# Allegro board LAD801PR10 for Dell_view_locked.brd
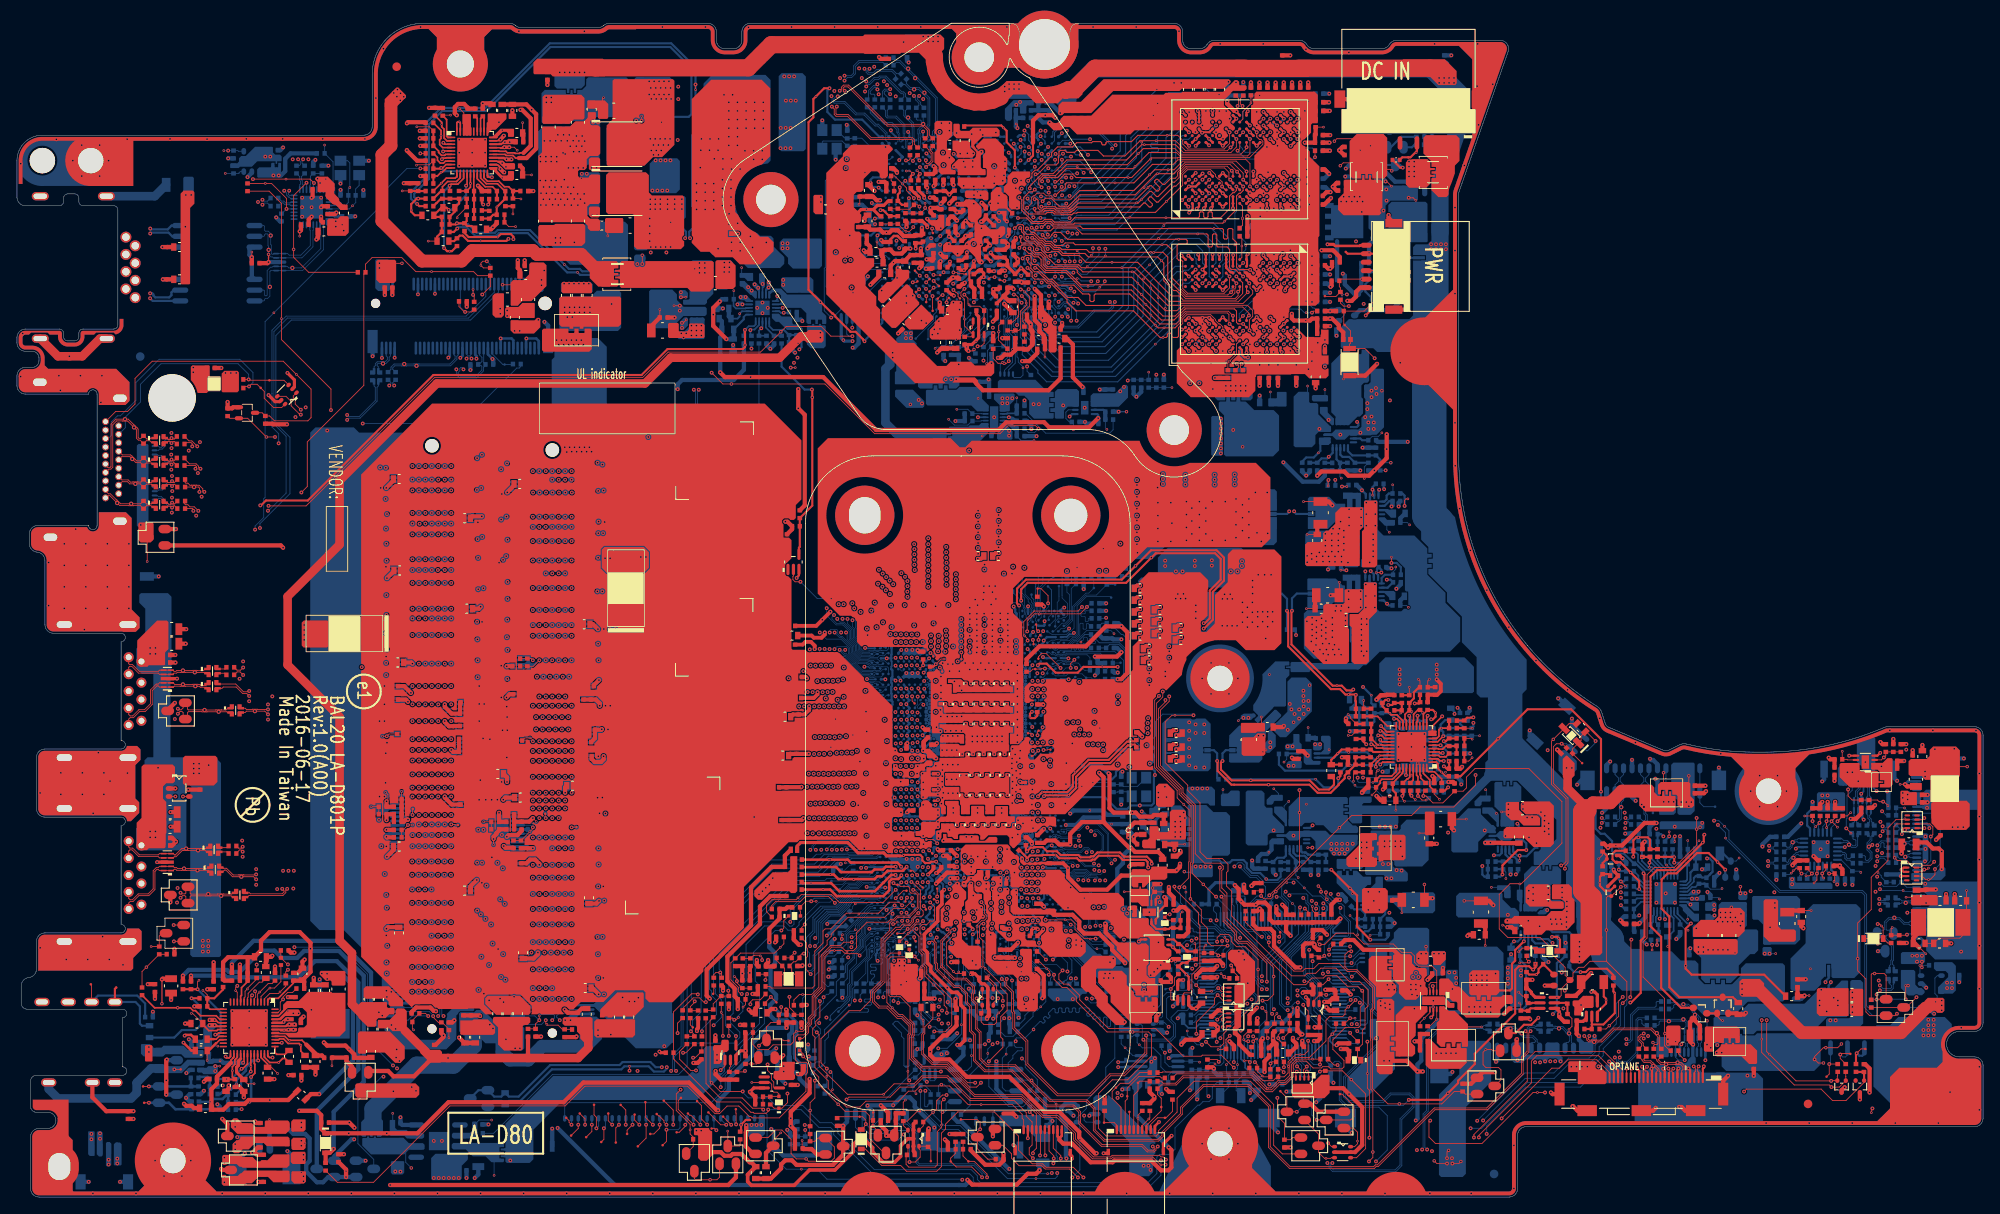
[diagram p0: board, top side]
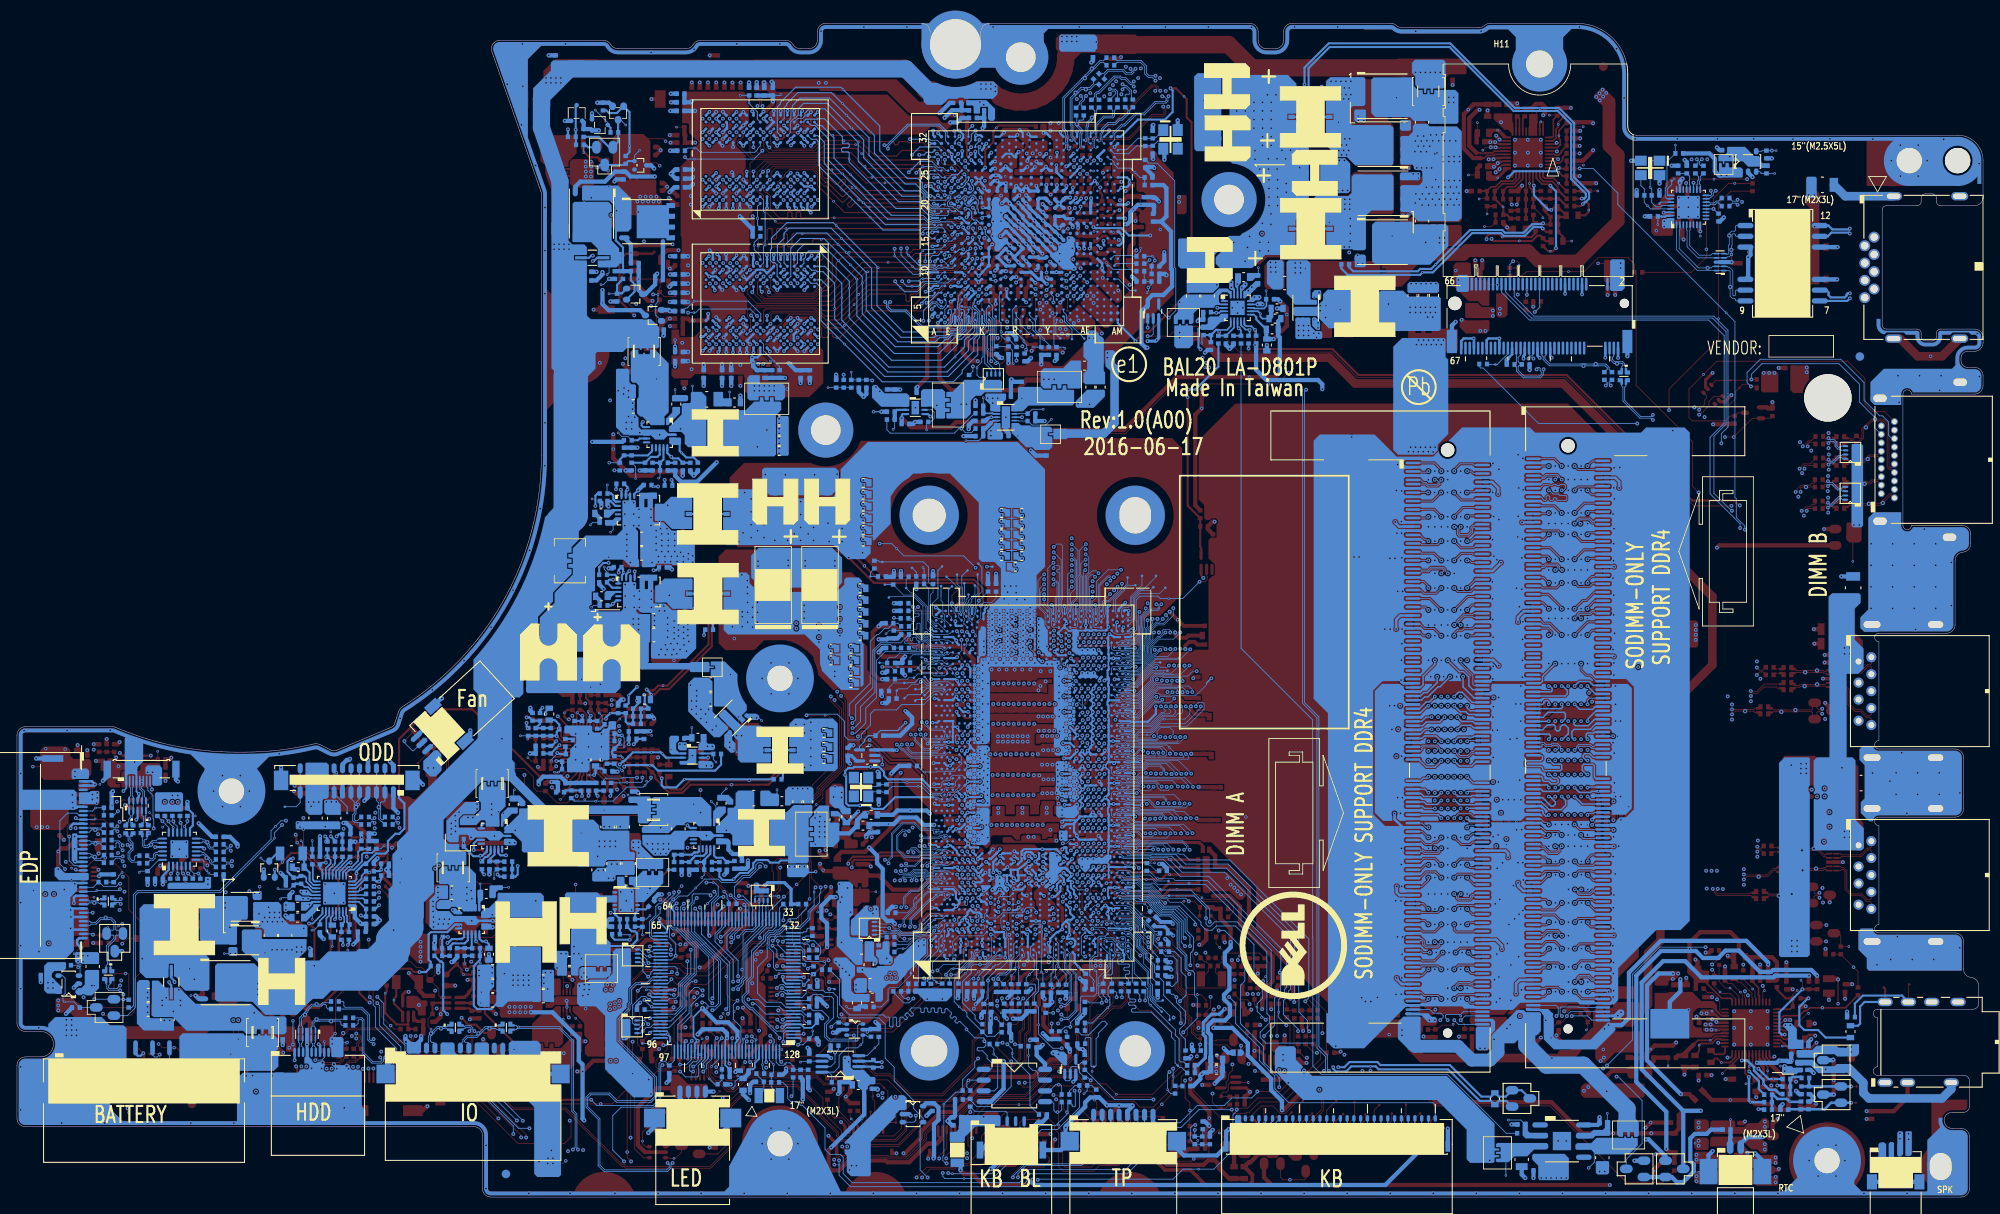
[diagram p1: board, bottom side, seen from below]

Outline 231.9 x 138.5 mm; copper layers: TOP, GND1, IN1, VCC, IN2, IN3, GND2, BOTTOM. Coordinates in mm from the lower left corner of the outline.
Outline path: 0,122.3 arc(0.88,124.42) 3,125.3 40.9,125.3 arc(41.61,125.59) 41.9,126.3 41.9,132.5 arc(43.66,136.74) 47.9,138.5 58.13,138.5 arc(58.49,138.44) 58.8,138.25 arc(59.1,138.06) 59.46,138 68.54,138 arc(68.9,138.06) 69.2,138.25 arc(69.51,138.44) 69.87,138.5 81.5,138.5 arc(82.21,138.21) 82.5,137.5 82.5,136.5 arc(82.79,135.79) 83.5,135.5 84.5,135.5 arc(85.21,135.79) 85.5,136.5 85.5,137.5 arc(85.79,138.21) 86.5,138.5 117.2,138.5 arc(117.91,138.21) 118.2,137.5 118.2,136 arc(121.2,133) 124.2,136 124.2,137.5 arc(124.49,138.21) 125.2,138.5 136.5,138.5 arc(137.21,138.21) 137.5,137.5 137.5,136.5 arc(137.79,135.79) 138.5,135.5 139.5,135.5 arc(140,135.63) 140.37,136 arc(140.73,136.37) 141.23,136.5 151.27,136.5 arc(151.77,136.37) 152.13,136 arc(152.5,135.63) 153,135.5 161,135.5 arc(161.5,135.63) 161.87,136 arc(162.23,136.37) 162.73,136.5 174.94,136.5 arc(175.76,136.08) 175.88,135.17 170.11,118.66 arc(170.06,118.5) 170.05,118.33 170.05,87.5 arc(174.41,70.58) 186.41,57.88 arc(186.71,57.6) 186.91,57.23 187.34,55.9 arc(187.51,55.61) 187.79,55.41 194.19,52.72 arc(194.52,52.66) 194.85,52.74 196.1,53.36 arc(196.5,53.48) 196.92,53.46 arc(200.96,52.74) 205.05,52.5 206.05,52.5 arc(213.3,53.24) 220.25,55.42 arc(220.44,55.48) 220.64,55.5 230.9,55.5 arc(231.61,55.21) 231.9,54.5 231.9,20.54 arc(231.61,19.83) 230.9,19.54 229.1,19.54 arc(227.6,18.04) 229.1,16.54 230.9,16.54 arc(231.61,16.25) 231.9,15.54 231.9,9.3 arc(231.61,8.59) 230.9,8.3 178,8.3 arc(177.29,8.01) 177,7.3 177,1 arc(176.71,0.29) 176,0 2.6,0 arc(1.89,0.29) 1.6,1 1.6,7.1 arc(1.89,7.81) 2.6,8.1 3.65,8.1 arc(4.6,9.05) 3.65,10 2.3,10 arc(1.8,10.21) 1.6,10.7 1.6,13.67 arc(1.8,14.16) 2.3,14.37 12.45,14.37 arc(12.95,14.87) 12.45,15.37 12.45,21.17 arc(12.95,21.67) 12.45,22.17 1.2,22.17 arc(0.71,22.37) 0.5,22.87 0.5,24.91 arc(0.76,25.58) 1.4,25.9 arc(2.04,26.23) 2.3,26.9 2.3,30.17 arc(2.59,30.87) 3.3,31.17 12.28,31.17 arc(12.78,31.67) 12.28,32.17 12.28,43.83 arc(12.78,44.33) 12.28,44.83 3.3,44.83 arc(2.59,45.13) 2.3,45.83 2.3,51.87 arc(2.59,52.57) 3.3,52.87 12.28,52.87 arc(12.78,53.37) 12.28,53.87 12.28,65.53 arc(12.78,66.03) 12.28,66.53 4.3,66.53 arc(3.59,66.83) 3.3,67.53 3.3,75.1 arc(3.03,75.78) 2.38,76.1 arc(1.73,76.42) 1.46,77.09 1.46,78.25 arc(1.75,78.96) 2.46,79.25 8.45,79.25 arc(8.95,78.75) 9.45,79.25 9.45,94.75 arc(8.95,95.25) 8.45,94.75 1,94.75 arc(0.29,95.04) 0,95.75 0,96.9 arc(0.29,97.61) 1,97.9 1.8,97.9 arc(2.37,98.13) 2.6,98.7 2.6,99 arc(2.37,99.57) 1.8,99.8 1,99.8 arc(0.29,100.09) 0,100.8 0,101.42 arc(0.29,102.13) 1,102.42 5,102.42 arc(5.35,102.28) 5.5,101.92 5.5,101.52 arc(5.65,101.17) 6,101.02 6.8,101.02 arc(7.15,101.17) 7.3,101.52 7.3,101.92 arc(7.45,102.28) 7.8,102.42 11.4,102.42 arc(11.75,102.57) 11.9,102.92 11.9,116.48 arc(11.75,116.83) 11.4,116.98 7.8,116.98 arc(7.45,117.12) 7.3,117.48 7.3,117.88 arc(7.15,118.23) 6.8,118.38 6,118.38 arc(5.65,118.23) 5.5,117.88 5.5,117.48 arc(5.35,117.12) 5,116.98 1,116.98 arc(0.29,117.27) 0,117.98 0,122.3

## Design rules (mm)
net group AUD_SPK_L_C: nets AUD_SPK_L+_C AUD_SPK_L-_C
net group AUD_SPK_R_C: nets AUD_SPK_R+_C AUD_SPK_R-_C
net group AUDIO: nets DMIC_CLK DMIC_CLK_EDP
net group CB: nets CBN CBP
net group DDR-RESET: nets DDR4_DRAMRST# H_DRAMRST#
net group DP: nets CPU_DP3_AUXN CPU_DP3_AUXP
net group GT1: nets GT1N GT1P
net group HDMI_15: nets HDMI_HPD_B HDMI_PLL_GND
net group ISUM_GT: nets ISUMN_GT ISUMP_GT
net group ISUM_IA: nets ISUMN_IA ISUMP_IA
net group ISUM_VSA: nets ISUMN_VSA ISUMP_VSA
net group NCT7718_DX: nets NCT7718_DXN NCT7718_DXP
net group PCH_SMBCLK: nets PCH_SMBCLK PCH_SMBDATA
net group PCIE_CTX_C_SSDRX_P11: nets PCIE_CTX_C_SSDRX_N11 PCIE_CTX_C_SSDRX_P11
net group PCIE_CTX_C_SSDRX_P12: nets PCIE_CTX_C_SSDRX_N12 PCIE_CTX_C_SSDRX_P12
net group PCIE_RCOMP: nets PCIE_RCOMPN PCIE_RCOMPP
net group SML1CLK: nets SML1CLK SML1DATA
net group USB_PP6_C: nets USB_PN6_C USB_PP6_C
net group VSA_SEN: nets VSA_SEN+ VSA_SEN-
net group VSUM_VGA: nets VSUM+_VGA VSUM-_VGA
net group ASYNCHRONOUS SIGNALS: nets H_THERMTRIP#
net group ASYNCHRONOUS-SIGNALS: nets PECI_MEC1404 VIDALERT_N VIDSOUT XDP_OBS2_R XDP_OBS3_R
net group CLK: nets H_PROCHOT#
net group CLK-SINGLE: nets CLK_ITPXDP_P
net group CLOCK-S: nets CLK_PCI_LPDEBUG
net group DDR_A-CLK: nets DDR_A_CLK0 DDR_A_CLK1 DDR_A_CLK#0 DDR_A_CLK#1
net group DDR_A-CMD: nets DDR_A_ACT# DDR_A_ALERT# DDR_A_BG0 DDR_A_BG1 DDR_A_BS0 DDR_A_BS1 DDR_A_CAS# DDR_A_MA0 DDR_A_MA1 DDR_A_MA2 DDR_A_MA3 DDR_A_MA4 DDR_A_MA5 DDR_A_MA6 DDR_A_MA7 DDR_A_MA8 DDR_A_MA9 DDR_A_MA10 DDR_A_MA11 DDR_A_MA12 DDR_A_MA13 DDR_A_PAR DDR_A_RAS# DDR_A_WE#
net group DDR_A-CTRL: nets DDR_A_CKE0 DDR_A_CKE1 DDR_A_CKE2 DDR_A_CKE3 DDR_A_CS#0 DDR_A_CS#1 DDR_A_ODT0 DDR_A_ODT1
net group DDR_A-D0: nets DDR_A_D0 DDR_A_D1 DDR_A_D2 DDR_A_D3 DDR_A_D4 DDR_A_D5 DDR_A_D6 DDR_A_D7
net group DDR_A-D1: nets DDR_A_D8 DDR_A_D9 DDR_A_D10 DDR_A_D11 DDR_A_D12 DDR_A_D13 DDR_A_D14 DDR_A_D15
net group DDR_A-D2: nets DDR_A_D16 DDR_A_D17 DDR_A_D18 DDR_A_D19 DDR_A_D20 DDR_A_D21 DDR_A_D22 DDR_A_D23
net group DDR_A-D3: nets DDR_A_D24 DDR_A_D25 DDR_A_D26 DDR_A_D27 DDR_A_D28 DDR_A_D29 DDR_A_D30 DDR_A_D31
net group DDR_A-D4: nets DDR_A_D32 DDR_A_D33 DDR_A_D34 DDR_A_D35 DDR_A_D36 DDR_A_D37 DDR_A_D38 DDR_A_D39
net group DDR_A-D5: nets DDR_A_D40 DDR_A_D41 DDR_A_D42 DDR_A_D43 DDR_A_D44 DDR_A_D45 DDR_A_D46 DDR_A_D47
net group DDR_A-D6: nets DDR_A_D48 DDR_A_D49 DDR_A_D50 DDR_A_D51 DDR_A_D52 DDR_A_D53 DDR_A_D54 DDR_A_D55
net group DDR_A-D7: nets DDR_A_D56 DDR_A_D57 DDR_A_D58 DDR_A_D59 DDR_A_D60 DDR_A_D61 DDR_A_D62 DDR_A_D63
net group DDR_B-CLK: nets DDR_B_CLK0 DDR_B_CLK1 DDR_B_CLK#0 DDR_B_CLK#1
net group DDR_B-CMD: nets DDR_B_ACT# DDR_B_ALERT# DDR_B_BG0 DDR_B_BG1 DDR_B_BS0 DDR_B_BS1 DDR_B_CAS# DDR_B_MA0 DDR_B_MA1 DDR_B_MA2 DDR_B_MA3 DDR_B_MA4 DDR_B_MA5 DDR_B_MA6 DDR_B_MA7 DDR_B_MA8 DDR_B_MA9 DDR_B_MA10 DDR_B_MA11 DDR_B_MA12 DDR_B_MA13 DDR_B_PAR DDR_B_RAS# DDR_B_WE#
net group DDR_B-CTRL: nets DDR_B_CKE0 DDR_B_CKE1 DDR_B_CKE2 DDR_B_CKE3 DDR_B_CS#0 DDR_B_CS#1 DDR_B_ODT0 DDR_B_ODT1
net group DDR_B-D0: nets DDR_B_D0 DDR_B_D1 DDR_B_D2 DDR_B_D3 DDR_B_D4 DDR_B_D5 DDR_B_D6 DDR_B_D7
net group DDR_B-D1: nets DDR_B_D8 DDR_B_D9 DDR_B_D10 DDR_B_D11 DDR_B_D12 DDR_B_D13 DDR_B_D14 DDR_B_D15
net group DDR_B-D2: nets DDR_B_D16 DDR_B_D17 DDR_B_D18 DDR_B_D19 DDR_B_D20 DDR_B_D21 DDR_B_D22 DDR_B_D23
net group DDR_B-D3: nets DDR_B_D24 DDR_B_D25 DDR_B_D26 DDR_B_D27 DDR_B_D28 DDR_B_D29 DDR_B_D30 DDR_B_D31
net group DDR_B-D4: nets DDR_B_D32 DDR_B_D33 DDR_B_D34 DDR_B_D35 DDR_B_D36 DDR_B_D37 DDR_B_D38 DDR_B_D39
net group DDR_B-D5: nets DDR_B_D40 DDR_B_D41 DDR_B_D42 DDR_B_D43 DDR_B_D44 DDR_B_D45 DDR_B_D46 DDR_B_D47
net group DDR_B-D6: nets DDR_B_D48 DDR_B_D49 DDR_B_D50 DDR_B_D51 DDR_B_D52 DDR_B_D53 DDR_B_D54 DDR_B_D55
net group DDR_B-D7: nets DDR_B_D56 DDR_B_D57 DDR_B_D58 DDR_B_D59 DDR_B_D60 DDR_B_D61 DDR_B_D62 DDR_B_D63
net group DDR_DQS: nets DDR_A_DQS0 DDR_A_DQS1 DDR_A_DQS2 DDR_A_DQS3 DDR_A_DQS4 DDR_A_DQS5 DDR_A_DQS6 DDR_A_DQS7 DDR_A_DQS#0 DDR_A_DQS#1 DDR_A_DQS#2 DDR_A_DQS#3 DDR_A_DQS#4 DDR_A_DQS#5 DDR_A_DQS#6 DDR_A_DQS#7 DDR_B_DQS0 DDR_B_DQS1 DDR_B_DQS2 DDR_B_DQS3 DDR_B_DQS4 DDR_B_DQS5 DDR_B_DQS6 DDR_B_DQS7 DDR_B_DQS#0 DDR_B_DQS#1 DDR_B_DQS#2 DDR_B_DQS#3 DDR_B_DQS#4 DDR_B_DQS#5 DDR_B_DQS#6 DDR_B_DQS#7
net group DMIC: nets DMIC_DATA_EDP
net group EDP: nets EDP_AUX EDP_AUX# EDP_AUX_DN EDP_AUX_DP EDP_TX0 EDP_TX0# EDP_TX0_DN EDP_TX0_DP EDP_TX1 EDP_TX1# EDP_TX1_DN EDP_TX1_DP
net group EDP-RCOMP: nets EDP_COMP
net group EMC: nets BST1_VGA BST2_VGA BST_1.2V BST_1.2V_R BST_3V BST_5V BST_+1VALW BST_+1VALW_R GT_SW1 LANXIN LANXOUT LG1_VGA LG2_VGA LG_1.2V LGATE_CHG LX1_VGA LX2_VGA LX_1.2V LX_1.8VALW LX_3V LX_5V LX_+1VALW MCT0 MCT1 MEC_XTAL1 MEC_XTAL1_R MEC_XTAL2 PHASE_CHG SA_SW UG1_VGA UG2_VGA UG_1.2V UGATE_CHG
net group ESD: nets DRAM_RST H_CPUPWRGD H_CPUPWRGD_R IMVP_VR_ON PCH_DPWROK PCH_PLTRST# PCH_PLTRST#_EC PCH_RSMRST# POWER_SW#_MB POWER_SW_IN# RESET_OUT# RUNPWROK SIO_PWRBTN# SIO_SLP_S3# SYS_PWROK SYS_RESET# USB_OC#0_1 USB_OC#2_3 USB_OC#4_5
net group GPU-XTAL: nets XTALOUT
net group GSPI: nets 3D_CAM_EN 3D_CAM_EN_PCH FW_UPDATE FW_UPDATE_PCH NRB_BIT
net group HDA: nets HDA_CODEC_RST# HDA_CODEC_SDIN0 HDA_CODEC_SDOUT HDA_CODEC_SYNC HDA_RST# HDA_SDIN0 HDA_SDOUT HDA_SYNC
net group HDMI: nets HDMI_CLK HDMI_CLK# HDMI_CLK#_R HDMI_CLK#_R_C HDMI_CLK_R HDMI_CLK_R_C HDMI_DATA0 HDMI_DATA0# HDMI_DATA0#_R HDMI_DATA0#_R_C HDMI_DATA0_R HDMI_DATA0_R_C HDMI_DATA1 HDMI_DATA1# HDMI_DATA1#_R HDMI_DATA1#_R_C HDMI_DATA1_R HDMI_DATA1_R_C HDMI_DATA2 HDMI_DATA2# HDMI_DATA2#_R HDMI_DATA2#_R_C HDMI_DATA2_R HDMI_DATA2_R_C
net group I2C: nets DDC_CLK_HDMI DDC_DATA_HDMI I2C_SCL_TP I2C_SDA_TP I2C_SDA_TP_Q PCH_HDMI_CLK PCH_HDMI_DATA
net group KB: nets KB_DET# KSI0 KSI1 KSI2 KSI3 KSI4 KSI5 KSI6 KSI7 KSO0 KSO1 KSO2 KSO3 KSO4 KSO5 KSO6 KSO7 KSO8 KSO9 KSO10 KSO11 KSO12 KSO13 KSO14 KSO15 KSO16
net group LAN: nets LAN_MDI0N LAN_MDI0P LAN_MDI1N LAN_MDI1P
net group LPC: nets LPC_LAD0 LPC_LAD1 LPC_LAD2 LPC_LAD3
net group MDI: nets MDO0+ MDO0- MDO1+ MDO1-
net group PCIE: nets LAN_TXN_C_PCH_RXN6 LAN_TXP_C_PCH_RXP6 PCIE_CRX_LANTX_N6 PCIE_CRX_LANTX_P6 PCIE_CRX_SSDTX_N11 PCIE_CRX_SSDTX_N12 PCIE_CRX_SSDTX_P11 PCIE_CRX_SSDTX_P12 PCIE_CRX_WLANTX_N5 PCIE_CRX_WLANTX_P5 PCIE_CTX_LANRX_N6 PCIE_CTX_LANRX_P6 PCIE_CTX_SSDRX_N11 PCIE_CTX_SSDRX_N12 PCIE_CTX_SSDRX_P11 PCIE_CTX_SSDRX_P12 PCIE_CTX_WLANRX_N5 PCIE_CTX_WLANRX_N5_C PCIE_CTX_WLANRX_P5 PCIE_CTX_WLANRX_P5_C PCIE_PTX_LANRX_N6_C PCIE_PTX_LANRX_P6_C PEG_GTX_C_HRX_N0 PEG_GTX_C_HRX_N1 PEG_GTX_C_HRX_N2 PEG_GTX_C_HRX_N3 PEG_GTX_C_HRX_P0 PEG_GTX_C_HRX_P1 PEG_GTX_C_HRX_P2 PEG_GTX_C_HRX_P3 PEG_GTX_HRX_N0 PEG_GTX_HRX_N1 PEG_GTX_HRX_N2 PEG_GTX_HRX_N3 PEG_GTX_HRX_P0 PEG_GTX_HRX_P1 PEG_GTX_HRX_P2 PEG_GTX_HRX_P3 PEG_HTX_C_GRX_N0 PEG_HTX_C_GRX_N1 PEG_HTX_C_GRX_N2 PEG_HTX_C_GRX_N3 PEG_HTX_C_GRX_P0 PEG_HTX_C_GRX_P1 PEG_HTX_C_GRX_P2 PEG_HTX_C_GRX_P3 PEG_HTX_GRX_N0 PEG_HTX_GRX_N1 PEG_HTX_GRX_N2 PEG_HTX_GRX_N3 PEG_HTX_GRX_P0 PEG_HTX_GRX_P1 PEG_HTX_GRX_P2 PEG_HTX_GRX_P3
net group PLATFORM-CLK: nets CLK_ITPXDP_N CLK_PCIE_LAN_N2 CLK_PCIE_LAN_P2 CLK_PCIE_LAN_REQ# CLK_PCIE_LAN_REQ#_R CLK_PCIE_SSD_N3 CLK_PCIE_SSD_P3 CLK_PCIE_SSD_REQ# CLK_PCIE_WLAN_N1 CLK_PCIE_WLAN_P1 CLK_PCIE_WLAN_REQ# CLK_PCIE_WLAN_REQ#_R CLK_PEG_VGA# PCI_CLK_LPC1 PEG_CLKREQ# PEG_CLKREQ#_G XCLK_BIASREF XTAL24_IN XTAL24_OUT
net group RTC: nets PCH_RTCX2 PCH_RTCX2_R SRTCRST#
net group SATA: nets SATA3_CRX_HDDTX_N0 SATA3_CRX_HDDTX_P0 SATA3_CTX_HDDRX_N0 SATA3_CTX_HDDRX_P0 SATA_CRX_ODDTX_N1 SATA_CRX_ODDTX_P1 SATA_CTX_ODDRX_N1 SATA_CTX_ODDRX_P1 SATA_RXN0_R SATA_RXN2_R SATA_RXP0_R SATA_RXP2_R SATA_TXN0_R SATA_TXN2_R SATA_TXP0_R SATA_TXP2_R
net group SMBUS: nets CLK_SMB DAT_SMB PBAT_CHG_SMBDAT PCH_SMB_ALERT# SMBCLK SMBDATA SML0_SMBCLK SML0_SMBDATA THM_SML1_CLK THM_SML1_DATA VGA_SMB_CK3 VGA_SMB_DA3
net group SPACING-8: nets AUD_HP1_JACK_L AUD_HP1_JACK_L1 AUD_HP1_JACK_R AUD_HP1_JACK_R1 HPOUT_L HPOUT_R LINE1-L_C LINE1-L_R LINE1_L LINE1_R
net group SPACING-12: nets H_PROCHOT#_R SATA_LED# SATA_ODD_PRSNT# VCCST_PWRGD
net group SPACING-15: nets +MVREFSA CFG0 CFG1 CFG2 CFG3 CFG4 CFG5 CFG6 CFG7 CFG8 CFG9 CFG10 CFG11 CFG12 CFG13 CFG14 CFG15 CFG16 CFG17 CFG18 CFG19 CFG_RCOMP CLK_PCI_LPC_MEC CPU_XDP_TCK0 EC_SPI_CLK H_CATERR# H_VCCST_PWRGD HDA_BIT_CLK HDA_CODEC_BITCLK I2C_SCL_TP_Q PBAT_CHG_SMBCLK PCH_JTAG_TCK1 PCH_RTCRST# PCH_RTCX1 PCH_SPI_CLK_0_R PCH_SPI_CLK_R RING2 RING2_R SLEEVE SLEEVE_R SOC_XDP_TDI SOC_XDP_TDO SOC_XDP_TMS SOC_XDP_TRST# SUSCLK SUSCLK_EC SUSCLK_SSD SVI2_SVC SVI2_SVD SVI2_SVT USBCOMP XDP_OBS0_R XDP_OBS1_R XDP_PRDY# XDP_PREQ#
net group SPACING-18(15): nets N26505655 N26505677 PECI_EC VIDSCLK
net group SPACING-20: nets SM_RCOMP0 SM_RCOMP1 SM_RCOMP2
net group SPI: nets EC_SPI_CS0# EC_SPI_MISO EC_SPI_MOSI N28938912 PCH_SPI_CLK_R1 PCH_SPI_CS#0_R1 PCH_SPI_D0_0_R PCH_SPI_D0_R PCH_SPI_D0_R1 PCH_SPI_D1_0_R PCH_SPI_D1_R PCH_SPI_D1_R1 PCH_SPI_D2_0_R PCH_SPI_D2_R PCH_SPI_D2_R1 PCH_SPI_D3_0_R PCH_SPI_D3_R PCH_SPI_D3_R1
net group SPK: nets AUD_SPK_L+ AUD_SPK_L- AUD_SPK_R+ AUD_SPK_R-
net group SVID: nets H_CPU_SVIDALRT#
net group USB20: nets USB_CAMERA_EDP USB_CAMERA_EDP# USB_PN1 USB_PN1_C USB_PN2 USB_PN2_C USB_PN3 USB_PN3_C USB_PN5 USB_PN6 USB_PN7 USB_PN7_TPNL USB_PN8 USB_PN8_R USB_PP1 USB_PP1_C USB_PP2 USB_PP2_C USB_PP3 USB_PP3_C USB_PP5 USB_PP6 USB_PP7 USB_PP7_TPNL USB_PP8 USB_PP8_R
net group USB30: nets USB3_CRX_C_RD_DTX_N3 USB3_CRX_C_RD_DTX_P3 USB3_CRX_DTX_N1 USB3_CRX_DTX_N1_C USB3_CRX_DTX_N2 USB3_CRX_DTX_N2_C USB3_CRX_DTX_N3 USB3_CRX_DTX_P1 USB3_CRX_DTX_P1_C USB3_CRX_DTX_P2 USB3_CRX_DTX_P2_C USB3_CRX_DTX_P3 USB3_CRX_L_DTX_N3 USB3_CRX_L_DTX_P3 USB3_CRX_RD_DTX_N3 USB3_CRX_RD_DTX_P3 USB3_CTX_C_DRX_N3 USB3_CTX_C_DRX_P3 USB3_CTX_C_RD_DRX_N3 USB3_CTX_C_RD_DRX_P3 USB3_CTX_DRX_N1 USB3_CTX_DRX_N1_C USB3_CTX_DRX_N1_R USB3_CTX_DRX_N2 USB3_CTX_DRX_N2_C USB3_CTX_DRX_N2_R USB3_CTX_DRX_N3 USB3_CTX_DRX_P1 USB3_CTX_DRX_P1_C USB3_CTX_DRX_P1_R USB3_CTX_DRX_P2 USB3_CTX_DRX_P2_C USB3_CTX_DRX_P2_R USB3_CTX_DRX_P3 USB3_CTX_L_DRX_N3 USB3_CTX_L_DRX_P3 USB3_CTX_RD_DRX_N3 USB3_CTX_RD_DRX_P3
net group VRAM-CLK: nets M_CLK0 M_CLK1 M_CLK#0 M_CLK#1
net group VRAM-DBI: nets M_ADBI0 M_ADBI1 M_DBI0# M_DBI1# M_DBI2# M_DBI3# M_DBI4# M_DBI5# M_DBI6# M_DBI7#
net group VRAM-EDC: nets M_EDC_0 M_EDC_1 M_EDC_2 M_EDC_3 M_EDC_4 M_EDC_5 M_EDC_6 M_EDC_7
net group VRAM-WCK: nets M_WCKA0_0 M_WCKA0_0# M_WCKA0_1 M_WCKA0_1# M_WCKA1_0 M_WCKA1_0# M_WCKA1_1 M_WCKA1_1#
net group VRAM_CMD: nets M_CAS#0 M_CAS#1 M_CKE0 M_CKE1 M_CS0B#0 M_CS1B#0 M_RAS#0 M_RAS#1 M_WE#0 M_WE#1
net group VRAM_D0: nets M_DA0 M_DA1 M_DA2 M_DA3 M_DA4 M_DA5 M_DA6 M_DA7
net group VRAM_D1: nets M_DA8 M_DA9 M_DA10 M_DA11 M_DA12 M_DA13 M_DA14 M_DA15
net group VRAM_D2: nets M_DA16 M_DA17 M_DA18 M_DA19 M_DA20 M_DA21 M_DA22 M_DA23
net group VRAM_D3: nets M_DA24 M_DA25 M_DA26 M_DA27 M_DA28 M_DA29 M_DA30 M_DA31
net group VRAM_D4: nets M_DA32 M_DA33 M_DA34 M_DA35 M_DA36 M_DA37 M_DA38 M_DA39
net group VRAM_D5: nets M_DA40 M_DA41 M_DA42 M_DA43 M_DA44 M_DA45 M_DA46 M_DA47
net group VRAM_D6: nets M_DA48 M_DA49 M_DA50 M_DA51 M_DA52 M_DA53 M_DA54 M_DA55
net group VRAM_D7: nets M_DA56 M_DA57 M_DA58 M_DA59 M_DA60 M_DA61 M_DA62 M_DA63
net group VRAM_MA: nets M0_MA0 M0_MA1 M0_MA2 M0_MA3 M0_MA4 M0_MA5 M0_MA6 M0_MA7 M0_MA8 M1_MA0 M1_MA1 M1_MA2 M1_MA3 M1_MA4 M1_MA5 M1_MA6 M1_MA7 M1_MA8
net group XDP: nets PCH_RSMRST#_Q XDP_HOOK0 XDP_ITP_PMODE XDP_PRSENT_CPU XDP_SPI_IO2 XDP_SPI_SI
net group XTAL-15(18)-20(26): nets XTALIN
nets with their own width: min track width 0.254; nets CAP_LED EN_1.8VALW FB_1.8VALW JACK_PLUG V3D3_STB
nets with their own width: min track width 0.508; nets +0.6V_DDR_VTT +0.6VSP +0.95VSDGPU +0.95VSDGPU_ON +0.95VSDGPU_OUT +1.0V_AMPHYPLL +1.0V_APLL +1.0V_APLLEBB +1.0V_CLK2 +1.0V_CLK4 +1.0V_CLK5 +1.0V_MPHYGT +1.0V_PRIM +1.0V_SRAM +1.0V_VCCST +1.0V_VCCST_C +1.0V_VCCSTG +1.0V_XDP +1.0VS_VCCIO +1.2V_DDR +1.2VP +1.8V_AVDD +1.8V_PRIM +1.8VALWP +1.8VGS +1.8VGS_GPU_ON +1.8VGS_OUT +1VALWP +2.5V_MEM +2.5VP +3.3V_ALW_DSW +3.3V_SPI +3.3V_WLAN +3V_DVDD +3VALW +3VALW_EC +3VALW_PCH +3VALWP +3VGS +3VGS_GPU_ON +3VGS_OUT +3VLP +3VS +3VS_CAM +5V_AVDD +5V_CAM +5V_KB_BL +5V_PVDD +5VALW +5VALWP +5VS +17.4V_BATT+ +17.4V_BATT++ +19V_ADPIN +19V_VIN +19VB +19VB_1.2V +19VB_+1VALW +19VB_GPU +BIF_VDDC +DCBAT_CAM +DCBAT_LCD +DP_VDDC +DP_VDDR +FB0_VREFCL +FB0_VREFDL +FB1_VREFCL +FB1_VREFDL +LAN_VDD10 +LAN_VDD33 +LAN_VDDREG +LCDVDD +LCDVDD_LCD +MIC2-VREFO +MPLL_PVDD +MVREFDA +RTC_CELL +RTC_CELL_VBAT +RTC_VCC +SPLL_PVDD +SPLL_VDDC +TP_VDD +TPAN_VDD +TSVDD +V_DDR_REFA +V_DDR_REFA_R +V_DDR_REFB +V_DDR_REFB_R +VCC_CORE +VCC_CORE_G0 +VCC_CORE_G1 +VCC_GT +VCC_SA +VDD_CT +VDDR3 +VGA_CORE ACIN_CHG AUD_AGND EC_AGND GND RTC_PWR
nets with their own width: min track width 1.016; nets MCT
nets with their own width: min track width 2.032; nets USB20_VCCA

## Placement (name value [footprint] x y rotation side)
C1  0.47U_0402_6.3V6K  [C_0402]  35.88 8.79 0 top
C2  0.1U_0402_16V7K  [C_0402]  223.78 47.46 0 top
C3  1U_0402_10V6K  [C_0402]  223.78 46.57 0 top
C4  0.1U_0603_50V7K  [C_0603]  224.75 51.27 90 top
C5  1000P_0402_50V7K  [C_0402]  223.6 51.19 90 top
C6  0.1U_0402_16V7K  [C_0402]  220.73 42.12 0 bottom
C7  0.1U_0402_16V7K  [C_0402]  220.73 41.24 0 bottom
C8  0.1U_0402_16V7K  [C_0402]  220.73 40.35 0 bottom
C9  0.1U_0402_16V7K  [C_0402]  220.73 39.46 0 bottom
C10  0.1U_0402_16V7K  [C_0402]  220.73 43.01 0 bottom
C11  0.1U_0402_16V7K  [C_0402]  220.73 43.9 0 bottom
C13  10P_0402_50V8J  [C_0402]  220.49 37.15 90 bottom
C14  33P_0402_50V8J  [C_0402]  225.19 35.38 90 top
C15  4.7U_0603_6.3V6K  [C_0603]  224.05 34.82 90 top
C16  10P_0402_50V8J  [C_0402]  222.01 30.9 270 top
C17  1U_0402_6.3V6K  [C_0402]  228.17 26.19 0 bottom
C18  .1U_0402_16V7K  [C_0402]  93.55 5.66 90 top
C19  0.1U_0402_16V7K  [C_0402]  103.66 9.89 180 top
C20  10U_0603_6.3V6M  [C_0603]  131.97 13.23 0 bottom
C21  0.1U_0402_16V7K  [C_0402]  131.06 13.69 270 bottom
C22  470P_0603_50V8J  [C_0603]  57.58 12.3 270 bottom
C23  2200P_0402_50V7K  [C_0402]  130.88 15.27 90 bottom
C24  0.1U_0402_16V7K  [C_0402]  135.79 13.55 180 bottom
C25  0.1U_0402_16V7K  [C_0402]  135.01 17.86 0 bottom
C26  10P_0402_50V8J  [C_0402]  110.72 5.65 180 top
C27  10P_0402_50V8J  [C_0402]  111.58 5.65 0 top
C30  22U_0805_10V6M  [C_0805]  194.48 45.55 270 bottom
C32  0.1U_0402_16V7K  [C_0402]  92.1 7.14 270 bottom
C33  100P_0402_50V8J  [C_0402]  92.98 7.15 270 bottom
C34  .1U_0402_16V7K  [C_0402]  120.53 8.47 0 bottom
CA1  10U_0603_10V6M  [C_0603]  35.01 23.65 90 top
CA2  .1U_0402_16V7K  [C_0402]  32.85 22.68 90 top
CA3  10U_0603_10V6M  [C_0603]  36.34 23.65 90 top
CA4  .1U_0402_16V7K  [C_0402]  33.48 19.63 90 top
CA5  4.7U_0603_6.3V6K  [C_0603]  28.02 28.34 0 top
CA6  .1U_0402_16V7K  [C_0402]  27.21 26.44 180 top
CA7  .1U_0402_16V7K  [C_0402]  22.45 22.5 180 top
CA9  6.8P_0402_50V  [C_0402]  31.12 29.1 0 top
CA10  .1U_0402_16V7K  [C_0402]  23.59 13.93 180 top
CA11  4.7U_0603_10V6K  [C_0603]  22.94 10.5 180 top
CA12  4.7U_0603_6.3V6K  [C_0603]  35.21 16.7 270 top
CA13  4.7U_0603_6.3V6K  [C_0603]  41.75 16.48 90 top
CA14  .1U_0402_16V7K  [C_0402]  40.65 16.42 90 top
CA15  4.7U_0603_6.3V6K  [C_0603]  33.67 25.61 90 top
CA16  .1U_0402_16V7K  [C_0402]  32.59 25.54 90 top
CA17  .1U_0402_16V7K  [C_0402]  27.21 25.55 180 top
CA20  4.7U_0603_6.3V6K  [C_0603]  24.66 12.47 90 top
CA21  10U_0603_6.3V6M  [C_0603]  33.98 15.31 90 top
CA22  4.7U_0603_6.3V6K  [C_0603]  29.36 27.2 270 top
CA23  2.2U_0603_6.3V6K  [C_0603]  26.75 13.87 270 top
CA24  1U_0603_16V7  [C_0603]  32.09 15.9 90 top
CA25  1U_0603_16V7  [C_0603]  29.56 13.92 90 top
CA26  10U_0603_6.3V6M  [C_0603]  21.93 20.47 180 top
CA27  1000P_0402_50V7K  [C_0402]  28.72 6.77 270 top
CA28  1000P_0402_50V7K  [C_0402]  28.72 7.82 90 top
CA29  1000P_0402_50V7K  [C_0402]  29.1 2.7 270 top
CA30  1000P_0402_50V7K  [C_0402]  29.1 4.08 90 top
CA31  0.1U_0402_16V7K  [C_0402]  14.75 24.73 270 top
CA32  10U_0603_10V6M  [C_0603]  22.43 17.3 180 top
CA33  10U_0603_10V6M  [C_0603]  22.43 18.63 180 top
CA34  100P_0402_50V8J  [C_0402]  20.53 13.05 270 bottom
CA35  100P_0402_50V8J  [C_0402]  20.59 10.36 90 bottom
CA36  100P_0402_50V8J  [C_0402]  20.7 15.92 270 bottom
CA37  100P_0402_50V8J  [C_0402]  20.59 16.9 90 bottom
CC1  0.1U_0402_16V7K  [C_0402]  90.82 77.29 90 top
CC2  33P_0402_50V8J  [C_0402]  104.6 11.76 90 bottom
CC3  0.1U_0402_25V6  [C_0402]  111.63 17.65 90 bottom
CC4  1U_0402_6.3V6K  [C_0402]  92.54 21.5 270 top
CC5  1U_0402_6.3V6K  [C_0402]  89.86 21.49 0 top
CC6  15P_0402_50V8J  [C_0402]  130.24 48.69 90 bottom
CC7  15P_0402_50V8J  [C_0402]  130.24 47.83 270 bottom
CC8  6.8P_0402_50V8C  [C_0402]  91.13 27.27 0 top
CC9  6.8P_0402_50V8C  [C_0402]  90.26 27.27 180 top
CC10  1U_0402_6.3V6K  [C_0402]  84.03 14.77 270 top
CC11  0.1U_0402_10V7K  [C_0402]  82.38 17.54 90 top
CC12  0.1U_0402_16V7K  [C_0402]  91.29 14.15 270 top
CC13  0.1U_0402_16V7K  [C_0402]  133.9 52.09 90 bottom
CC14  1U_0402_6.3V6K  [C_0402]  87.99 11.84 180 top
CC15  100P_0402_50V8J  [C_0402]  124.91 72.35 0 bottom
CC16  22P_0402_50V8J  [C_0402]  80.73 17.18 270 top
CC26  10U_0402_6.3V6M  [C_0402]  90.76 47.45 90 top
CC27  10U_0402_6.3V6M  [C_0402]  91.97 51.38 90 top
CC28  10U_0402_6.3V6M  [C_0402]  91.64 61.36 0 top
CC29  10U_0402_6.3V6M  [C_0402]  91.08 43.57 90 top
CC30  10U_0402_6.3V6M  [C_0402]  90.19 43.57 90 top
CC31  10U_0402_6.3V6M  [C_0402]  88.97 48.35 0 top
CC32  1U_0402_6.3V6K  [C_0402]  104.9 48.91 90 top
CC33  1U_0402_6.3V6K  [C_0402]  104.92 52.02 90 top
CC34  1U_0402_6.3V6K  [C_0402]  92.22 56.03 90 top
CC35  1U_0402_6.3V6K  [C_0402]  91.78 64.27 90 top
CC36  22U_0603_6.3V6M  [C_0603]  89.62 52.09 0 top
CC37  22U_0603_6.3V6M  [C_0603]  89.87 56.68 0 top
CC38  22U_0603_6.3V6M  [C_0603]  90.7 66.25 0 top
CC39  10U_0402_6.3V6M  [C_0402]  90.87 67.4 0 top
CC40  1U_0402_6.3V6K  [C_0402]  105.35 42.89 0 top
CC41  1U_0402_6.3V6K  [C_0402]  131.83 38.37 90 top
CC42  1U_0402_6.3V6K  [C_0402]  120.35 41.79 90 top
CC43  1U_0402_6.3V6K  [C_0402]  91.57 58.89 0 top
CC44  1U_0402_6.3V6K  [C_0402]  132.73 38.37 90 top
CC45  1U_0402_6.3V6K  [C_0402]  106.65 45.62 180 top
CC46  1U_0402_6.3V6K  [C_0402]  107.65 52.11 270 top
CC47  1U_0402_6.3V6K  [C_0402]  107.08 44.74 270 top
CC48  1U_0402_6.3V6K  [C_0402]  107.97 44.74 270 top
CC49  10U_0402_6.3V6M  [C_0402]  106.94 53.36 0 top
CC50  10U_0402_6.3V6M  [C_0402]  107.46 54.24 90 top
CC51  1U_0402_6.3V6K  [C_0402]  106.11 25.17 0 top
CC52  1U_0402_6.3V6K  [C_0402]  106.11 24.29 0 top
CC53  1U_0402_6.3V6K  [C_0402]  106.11 23.42 0 top
CC54  1U_0402_6.3V6K  [C_0402]  105.73 26.69 0 top
CC55  1U_0402_6.3V6K  [C_0402]  117.61 36.99 180 top
CC56  1U_0402_6.3V6K  [C_0402]  105.85 26.35 270 bottom
CC57  1U_0402_6.3V6K  [C_0402]  110 39.06 90 top
CC58  1U_0402_6.3V6K  [C_0402]  115.08 41.22 90 top
CC59  47U_0805_6.3V6M  [C_0805]  130.41 25 0 bottom
CC60  1U_0402_6.3V6K  [C_0402]  116.22 32.74 270 top
CC61  8.2P_0402_50V8D  [C_0402]  90.57 38.96 270 top
CC62  1U_0402_6.3V6K  [C_0402]  110.15 40.92 180 top
CC63  1U_0402_6.3V6K  [C_0402]  130.35 44.01 270 bottom
CC64  1U_0402_6.3V6K  [C_0402]  113.58 38.3 0 top
CC65  1P_0402_50V8  [C_0402]  109.02 38.92 180 top
CC66  1U_0402_6.3V6K  [C_0402]  114.45 35.44 180 top
CC67  1U_0402_6.3V6K  [C_0402]  133.2 31.55 0 bottom
CC68  1U_0402_6.3V6K  [C_0402]  111.25 34.56 0 top
CC69  0.1U_0402_10V7K  [C_0402]  97.01 29.84 180 bottom
CC70  0.1U_0402_10V7K  [C_0402]  90.75 35.52 90 top
CC71  1U_0402_6.3V6K  [C_0402]  89.85 35.52 90 top
CC72  1U_0402_6.3V6K  [C_0402]  116.86 28.26 90 top
CC73  0.1U_0402_10V7K  [C_0402]  132.56 26.9 90 bottom
CC74  47U_0805_6.3V6M  [C_0805]  131.44 29.45 0 bottom
CC75  1U_0402_6.3V6K  [C_0402]  120.26 33.69 90 top
CC76  47U_0603_6.3V6M  [C_0603]  136.53 41.63 270 top
CC77  47U_0603_6.3V6M  [C_0603]  135.25 45.08 90 top
CC78  0.1U_0402_10V7K  [C_0402]  113.47 36.32 180 top
CC79  1U_0402_6.3V6K  [C_0402]  133.22 32.42 0 bottom
CC80  22U_0603_6.3V6M  [C_0603]  91.09 16.25 180 bottom
CC81  22U_0603_6.3V6M  [C_0603]  91.12 15.03 180 bottom
CC82  8.2P_0402_50V8D  [C_0402]  133.04 41.64 180 top
CC83  0.1U_0603_25V7K  [C_0603]  132.8 44.18 270 top
CC84  47U_0603_6.3V6M  [C_0603]  134.08 44.16 90 bottom
CC85  1U_0402_6.3V6K  [C_0402]  110.83 21.18 90 top
CC86  1U_0402_6.3V6K  [C_0402]  111.82 27.75 180 top
CC87  1U_0402_6.3V6K  [C_0402]  115.97 28.27 90 top
CC88  10P_0402_50V8J  [C_0402]  94.06 17.29 270 bottom
CC89  1P_0402_50V8  [C_0402]  80.35 22.01 270 top
CC90  100P_0402_50V8J  [C_0402]  92.34 79.15 180 top
CD1  10U_0603_6.3V6M~D  [C_0603]  72.22 20.53 90 top
CD2  10U_0603_6.3V6M~D  [C_0603]  71.01 20.53 90 top
CD3  1U_0402_6.3V6K~D  [C_0402]  69.93 20.52 90 top
CD4  1U_0402_6.3V6K~D  [C_0402]  69.04 20.52 90 top
CD5  1U_0402_6.3V6K~D  [C_0402]  60.15 20.9 90 top
CD6  10U_0603_6.3V6M~D  [C_0603]  56.66 20.92 90 top
CD7  10U_0603_6.3V6M~D  [C_0603]  57.87 20.92 90 top
CD8  10U_0603_6.3V6M~D  [C_0603]  59.07 20.92 90 top
CD9  0.1U_0402_16V7K~D  [C_0402]  66.12 20.84 90 top
CD10  2.2U_0603_6.3V6K~D  [C_0603]  67.2 20.85 90 top
CD11  1U_0402_6.3V6K~D  [C_0402]  59.45 40.3 270 top
CD12  1U_0402_6.3V6K~D  [C_0402]  66.87 52.03 0 top
CD13  1U_0402_6.3V6K~D  [C_0402]  67.13 60.29 0 top
CD14  1U_0402_6.3V6K~D  [C_0402]  66.81 53.68 0 top
CD15  1U_0402_6.3V6K~D  [C_0402]  67.71 57.8 90 top
CD16  1U_0402_6.3V6K~D  [C_0402]  66.82 57.8 90 top
CD17  1U_0402_6.3V6K~D  [C_0402]  67.25 55.14 0 top
CD18  1U_0402_6.3V6K~D  [C_0402]  59.47 59.33 180 top
CD19  10U_0603_6.3V6M~D  [C_0603]  60.09 47.14 180 top
CD20  10U_0603_6.3V6M~D  [C_0603]  66.25 48.54 180 top
CD21  10U_0603_6.3V6M~D  [C_0603]  59.71 29.55 270 top
CD22  10U_0603_6.3V6M~D  [C_0603]  66.19 67.59 0 top
CD23  10U_0603_6.3V6M~D  [C_0603]  60.03 84.16 180 top
CD24  10U_0603_6.3V6M~D  [C_0603]  66.31 24.66 0 top
CD25  10U_0603_6.3V6M~D  [C_0603]  67.46 36.03 270 top
CD26  10U_0603_6.3V6M~D  [C_0603]  55.99 49.94 0 top
CD27  330U_D2_2V_Y  [C_D2]  41.83 66.5 180 top
CD28  0.1U_0402_16V7K~D  [C_0402]  59.52 44.3 270 top
CD29  0.1U_0402_16V7K~D  [C_0402]  59.35 62.65 180 top
CD30  0.022U_0402_25V7K  [C_0402]  56.86 43.39 180 top
CD31  1U_0402_6.3V6K~D  [C_0402]  44.21 21.98 90 top
CD32  10U_0603_6.3V6M~D  [C_0603]  41.93 20.53 270 top
CD33  10U_0603_6.3V6M~D  [C_0603]  41.48 22.63 90 top
CD34  10U_0603_6.3V6M~D  [C_0603]  42.69 22.63 90 top
CD35  1U_0402_6.3V6K~D  [C_0402]  52.66 20.52 90 top
CD36  1U_0402_6.3V6K~D  [C_0402]  53.55 20.52 90 top
CD37  10U_0603_6.3V6M~D  [C_0603]  54.06 19.58 270 top
CD38  10U_0603_6.3V6M~D  [C_0603]  52.85 19.58 270 top
CD39  0.1U_0402_16V7K~D  [C_0402]  45.1 21.98 90 top
CD40  2.2U_0603_6.3V6K~D  [C_0603]  43.14 20.53 270 top
CD41  1U_0402_6.3V6K~D  [C_0402]  44.01 58.7 0 top
CD42  1U_0402_6.3V6K~D  [C_0402]  44.01 60.29 0 top
CD43  1U_0402_6.3V6K~D  [C_0402]  53.24 46.32 180 top
CD44  1U_0402_6.3V6K~D  [C_0402]  53.05 52.54 180 top
CD45  1U_0402_6.3V6K~D  [C_0402]  53.05 54.06 180 top
CD46  1U_0402_6.3V6K~D  [C_0402]  53.18 55.59 180 top
CD47  1U_0402_6.3V6K~D  [C_0402]  53.18 57.05 180 top
CD48  1U_0402_6.3V6K~D  [C_0402]  53.24 58.38 180 top
CD49  10U_0603_6.3V6M~D  [C_0603]  52.09 36.16 0 top
CD50  10U_0603_6.3V6M~D  [C_0603]  52.09 80.1 0 top
CD51  10U_0603_6.3V6M~D  [C_0603]  44.21 63.08 0 top
CD52  10U_0603_6.3V6M~D  [C_0603]  45.87 73.94 180 top
CD53  10U_0603_6.3V6M~D  [C_0603]  45.8 84.73 180 top
CD54  10U_0603_6.3V6M~D  [C_0603]  45.8 41.36 180 top
CD55  10U_0603_6.3V6M~D  [C_0603]  52.34 69.43 0 top
CD56  10U_0603_6.3V6M~D  [C_0603]  45.04 30.44 90 top
CD57  330U_D2_2V_Y  [C_D2]  71.84 68.64 90 top
CD58  0.1U_0402_16V7K~D  [C_0402]  45.37 44.28 180 top
CD59  0.022U_0402_25V7K  [C_0402]  43.59 46.06 180 top
CE1  0.1U_0402_10V7K  [C_0402]  150.12 19.63 0 top
CE2  0.1U_0402_10V7K  [C_0402]  148.75 15.07 180 bottom
CE3  10P_0402_50V8J  [C_0402]  143.81 13.6 0 bottom
CE4  10P_0402_50V8J  [C_0402]  142.91 14.44 180 bottom
CE5  10U_0603_6.3V6M  [C_0603]  155.52 23.42 270 top
CE6  0.1U_0402_10V7K  [C_0402]  140.87 26.82 270 top
CE7  1000P_0402_50V7K  [C_0402]  146.84 32.8 0 top
CE8  1000P_0402_50V7K  [C_0402]  149.69 33.31 270 top
CE9  0.1U_0402_25V6  [C_0402]  152.86 32.42 270 top
CE10  0.1U_0402_25V6  [C_0402]  155.42 24.38 0 top
CE11  0.1U_0402_25V6  [C_0402]  151.8 17.73 180 top
CE12  0.1U_0402_25V6  [C_0402]  140.86 20.39 90 top
CE13  0.1U_0402_25V6  [C_0402]  146.77 16.7 0 top
CE14  0.1U_0402_10V7K  [C_0402]  145.61 14.91 0 bottom
CE15  0.1U_0402_25V6  [C_0402]  148.8 32.4 90 top
CE16  100P_0402_50V8J  [C_0402]  154.96 15.52 270 bottom
CE17  0.1U_0402_25V6  [C_0402]  157.12 18.13 270 top
CE18  0.1U_0402_10V7K  [C_0402]  154.12 33.36 0 top
CE19  0.047U_0402_16V4Z  [C_0402]  146.77 36.14 90 top
CE20  0.1U_0402_25V6  [C_0402]  140 26.83 270 top
CE21  0.1U_0402_25V6  [C_0402]  146.74 17.59 0 top
CE22  0.1U_0402_10V7K  [C_0402]  153.69 20.03 270 top
CE23  0.1U_0402_25V6  [C_0402]  140.01 28.79 270 top
CE24  1U_0603_16V7  [C_0603]  139.72 24.28 270 top
CE25  2200P_0402_25V7K  [C_0402]  149.45 18.06 180 top
CE26  47P_0402_50V8J  [C_0402]  152.29 20.03 270 top
CE27  0.047U_0402_16V4Z  [C_0402]  151.48 33.3 180 top
CE28  220P_0402_50V8J  [C_0402]  144.91 33.74 0 top
CE29  0.1U_0402_10V7K  [C_0402]  153.76 30.57 180 top
CE30  2200P_0402_25V7K  [C_0402]  148.32 20.46 270 top
CE31  1000P_0402_50V7K  [C_0402]  152.69 28.47 180 top
CE32  100P_0402_50V8J  [C_0402]  140.42 15.31 90 top
CE33  1U_0402_6.3V6K  [C_0402]  138.58 15.02 270 bottom
CI1  0.1U_0402_10V7K  [C_0402]  19.77 87.21 180 top
CI2  0.1U_0402_10V7K  [C_0402]  19.77 86.32 180 top
CI3  0.1U_0402_10V7K  [C_0402]  19.77 89.75 180 top
CI4  0.1U_0402_10V7K  [C_0402]  19.77 88.86 180 top
CI5  0.1U_0402_10V7K  [C_0402]  19.83 84.67 180 top
CI6  0.1U_0402_10V7K  [C_0402]  19.83 83.78 180 top
CI7  0.1U_0402_10V7K  [C_0402]  19.83 82.13 180 top
CI8  0.1U_0402_10V7K  [C_0402]  19.83 81.24 180 top
CI9  .1U_0402_16V7K  [C_0402]  22.4 97.83 0 top
CL1  0.1U_0402_10V7K  [C_0402]  32.98 121.7 270 bottom
CL2  0.1U_0402_10V7K  [C_0402]  33.93 121.7 270 bottom
CL3  0.1U_0402_10V7K  [C_0402]  29.91 116.93 0 bottom
CL4  0.1U_0402_10V7K  [C_0402]  29.91 117.88 0 bottom
CL5  0.1U_0402_25V6  [C_0402]  33.5 114.75 0 top
CL6  0.1U_0402_25V6  [C_0402]  36.65 115.99 90 top
CL7  4.7U_0603_6.3V6K  [C_0603]  36.91 113.94 180 top
CL8  0.1U_0402_25V6  [C_0402]  36.99 115.02 180 top
CL9  1U_0402_6.3V6K  [C_0402]  29.85 123.53 0 bottom
CL10  10P_0402_50V8J  [C_0402]  39.08 118.2 180 bottom
CL11  10P_0402_50V8J  [C_0402]  39.95 118.2 0 bottom
CL12  0.01U_0402_16V7K  [C_0402]  27.69 110.2 0 top
CL13  100P_1206_2KV8J  [C_1206]  20.26 119.44 180 bottom
CL14  0.1U_0402_25V6  [C_0402]  35.78 118.92 180 top
CS1  0.01U_0402_50V7K  [C_0402]  193.94 23.08 0 bottom
CS2  0.01U_0402_50V7K  [C_0402]  193.94 22.19 0 bottom
CS3  0.01U_0402_50V7K  [C_0402]  192.24 21.15 0 bottom
CS4  0.01U_0402_50V7K  [C_0402]  192.24 20.26 0 bottom
CS5  1000P_0402_50V7K  [C_0402]  199.42 18.76 180 top
CS6  0.1U_0402_25V6K  [C_0402]  199.42 19.65 180 top
CS7  10U_0805_10V6K  [C_0805]  195.64 19.07 0 top
CS9  0.01U_0402_50V7K  [C_0402]  191.29 43.97 180 bottom
CS10  0.01U_0402_50V7K  [C_0402]  191.29 44.85 180 bottom
CS11  0.01U_0402_50V7K  [C_0402]  188.5 43.97 180 bottom
CS12  0.01U_0402_50V7K  [C_0402]  188.5 44.85 180 bottom
CS13  1000P_0402_50V7K  [C_0402]  196.98 47.65 0 top
CS14  0.1U_0402_25V6K  [C_0402]  196.98 48.54 0 top
CS15  10U_0805_10V6K  [C_0805]  196.68 45.57 270 bottom
CS16  0.22U_0402_16V7K  [C_0402]  191.29 17.49 270 top
CS17  0.22U_0402_16V7K  [C_0402]  192.18 17.5 270 top
CS18  0.22U_0402_16V7K  [C_0402]  193.06 17.49 270 top
CS19  0.22U_0402_16V7K  [C_0402]  193.95 17.49 270 top
CU1  .1U_0402_16V7K  [C_0402]  25.62 62.51 180 top
CU2  .1U_0402_16V7K  [C_0402]  25.62 61.62 180 top
CU3  .1U_0402_16V7K  [C_0402]  25.88 41.43 180 top
CU4  .1U_0402_16V7K  [C_0402]  25.88 40.54 180 top
CU5  1U_0402_10V6K  [C_0402]  21.61 48.99 270 top
CU6  1U_0402_10V6K  [C_0402]  17.15 63.97 0 top
CU7  1U_0402_10V6K  [C_0402]  17.15 42.38 0 top
CU8  22U_0805_10V6M  [C_0805]  17.2 43.71 0 top
CU9  22U_0805_10V6M  [C_0805]  17.39 65.3 0 top
CU10  100U_1206_6.3V6M  [C_1206]  15.7 48.85 180 bottom
CU17  .1U_0402_16V7K  [C_0402]  123.93 11.07 270 bottom
CU18  1U_0402_10V6K  [C_0402]  17.15 63.07 0 top
CU19  1U_0402_10V6K  [C_0402]  17.15 41.48 0 top
CU20  22U_0805_10V6M  [C_0805]  17.39 67.01 0 top
CU21  22U_0805_10V6M  [C_0805]  17.2 45.42 0 top
CU22  100U_1206_6.3V6M  [C_1206]  15.32 70.57 90 bottom
CV1  0.22U_0402_16V7K  [C_0402]  100.28 129.51 270 bottom
CV2  0.22U_0402_16V7K  [C_0402]  101.18 129.51 270 bottom
CV3  0.22U_0402_16V7K  [C_0402]  102.09 129.49 270 bottom
CV4  0.22U_0402_16V7K  [C_0402]  102.99 129.49 270 bottom
CV5  0.22U_0402_16V7K  [C_0402]  106.23 123.85 270 top
CV6  0.22U_0402_16V7K  [C_0402]  105.33 123.85 270 top
CV7  0.22U_0402_16V7K  [C_0402]  107.12 124.93 270 top
CV8  0.22U_0402_16V7K  [C_0402]  108.01 124.93 270 top
CV11  0.082U_0402_16V  [C_0402]  103.9 114.83 90 top
CV15  0.68U_0402_10V  [C_0402]  103.45 118.69 180 top
CV17  10P_0402_50V8J  [C_0402]  97.94 124.92 90 bottom
CV18  10P_0402_50V8J  [C_0402]  97.94 124.05 270 bottom
CV19  10U_0603_6.3V6M  [C_0603]  100.31 114.47 90 top
CV20  1U_0402_6.3V4Z  [C_0402]  106.87 113.67 270 top
CV21  0.1U_0402_10V6K  [C_0402]  105.97 113.49 270 top
CV26  1U_0402_6.3V4Z  [C_0402]  103 111.78 90 top
CV27  10U_0603_6.3V6M  [C_0603]  102.02 111.51 180 top
CV28  0.68U_0402_10V  [C_0402]  105.79 117.08 180 top
CV29  0.68U_0402_10V  [C_0402]  106.6 116.09 270 top
CV30  10U_0603_6.3V6M  [C_0603]  104.71 110.43 270 top
CV33  1U_0402_6.3V4Z  [C_0402]  106.69 111.15 270 top
CV34  0.1U_0402_10V6K  [C_0402]  105.79 111.15 270 top
CV35  0.1U_0402_10V6K  [C_0402]  104.71 111.87 90 top
CV38  10U_0603_6.3V6M  [C_0603]  96.1 116.54 180 top
CV39  0.1U_0402_10V6K  [C_0402]  102.2 121.39 0 top
CV40  2.2U_0402_6.3V6M  [C_0402]  116.48 111.78 270 top
CV41  2.2U_0402_6.3V6M  [C_0402]  126.45 127.32 90 top
CV42  2.2U_0402_6.3V6M  [C_0402]  116.69 118.86 180 top
CV43  10U_0603_6.3V6M  [C_0603]  138.13 130.01 90 top
CV44  10U_0603_6.3V6M  [C_0603]  139.4 130.01 90 top
CV45  10U_0603_6.3V6M  [C_0603]  140.67 130.01 90 top
CV46  1U_0402_6.3V4Z  [C_0402]  99.32 113.43 0 top
CV47  2.2U_0402_6.3V6M  [C_0402]  135.78 129.92 90 top
CV48  2.2U_0402_6.3V6M  [C_0402]  124.67 127.32 90 top
CV49  0.1U_0402_10V6K  [C_0402]  117.37 117.89 180 top
CV50  0.1U_0402_10V6K  [C_0402]  136.67 129.92 90 top
CV51  0.1U_0402_10V6K  [C_0402]  115.58 111.78 270 top
CV52  0.1U_0402_10V6K  [C_0402]  117.73 109.98 180 top
CV53  0.1U_0402_10V6K  [C_0402]  117.37 116.99 180 top
CV54  10U_0603_6.3V6M  [C_0603]  105.29 96.28 270 bottom
CV55  10U_0603_6.3V6M  [C_0603]  104.08 96.28 270 bottom
CV56  1U_0402_6.3V4Z  [C_0402]  113.5 123.97 124.1 top
CV57  1U_0402_6.3V4Z  [C_0402]  112.16 119.96 90 top
CV58  1U_0402_6.3V4Z  [C_0402]  113.94 119.96 90 top
CV59  1U_0402_6.3V4Z  [C_0402]  113.05 119.96 90 top
CV60  1U_0402_6.3V4Z  [C_0402]  114.27 121.75 180 top
CV61  10U_0603_6.3V6M  [C_0603]  100.49 118.07 90 top
CV62  1U_0402_6.3V4Z  [C_0402]  108.39 117.71 90 top
CV63  0.1U_0402_10V6K  [C_0402]  109.38 117.8 90 top
CV64  1U_0402_6.3V4Z  [C_0402]  98.96 117.08 90 bottom
CV65  1U_0402_6.3V4Z  [C_0402]  108.12 114.92 90 top
CV66  1U_0402_6.3V4Z  [C_0402]  109.02 115.64 90 top
CV67  10U_0603_6.3V6M  [C_0603]  110.73 101.54 270 top
CV68  10U_0603_6.3V6M  [C_0603]  103.09 105.04 135 top
CV69  10U_0603_6.3V6M  [C_0603]  104.44 103.88 315 top
CV70  10U_0603_6.3V6M  [C_0603]  109.47 101.54 270 top
CV71  1U_0402_6.3V4Z  [C_0402]  111.43 112.84 270 top
CV72  1U_0402_6.3V4Z  [C_0402]  114.32 112.86 90 top
CV73  1U_0402_6.3V4Z  [C_0402]  112.52 108.01 0 top
CV74  1U_0402_6.3V4Z  [C_0402]  111.97 110.86 270 top
CV75  1U_0402_6.3V4Z  [C_0402]  114.32 110.95 180 top
CV76  1U_0402_6.3V4Z  [C_0402]  108.84 109.71 0 top
CV77  1U_0402_6.3V4Z  [C_0402]  111.61 114.53 180 top
CV78  1U_0402_6.3V4Z  [C_0402]  114.28 116.67 180 top
CV79  1U_0402_6.3V4Z  [C_0402]  115.22 114.65 270 top
CV80  1U_0402_6.3V4Z  [C_0402]  112.91 106.25 0 top
CV81  10U_0603_6.3V6M  [C_0603]  117.46 105.76 270 top
CV82  1U_0402_6.3V4Z  [C_0402]  116.39 106.3 180 top
CV84  10U_0603_6.3V6M  [C_0603]  121.18 101.11 180 top
CV85  1U_0402_6.3V4Z  [C_0402]  120.62 102.19 180 top
CV86  0.1U_0402_10V6K  [C_0402]  120.05 104.09 180 top
CV87  1U_0402_6.3V4Z  [C_0402]  117.01 114.11 180 top
CV88  10U_0603_6.3V6M  [C_0603]  110.46 104.69 180 top
CV89  1U_0402_6.3V4Z  [C_0402]  116.48 116.09 0 top
CV90  1U_0402_6.3V4Z  [C_0402]  115.22 115.73 90 top
CV91  10U_0603_6.3V6M  [C_0603]  122.19 101.3 0 top
CV92  1U_0402_6.3V4Z  [C_0402]  122.18 102.38 0 top
CV93  0.1U_0402_10V6K  [C_0402]  120.79 104.95 0 top
CV94  1U_0402_6.3V4Z  [C_0402]  117.82 127.34 180 bottom
CV95  1U_0402_6.3V4Z  [C_0402]  119.6 128.23 180 bottom
CV96  120P_0402_50V8J  [C_0402]  135.28 95.52 90 bottom
CV97  68P_0402_50V8J  [C_0402]  131.71 96.43 270 bottom
CV98  0.1U_0402_16V4Z  [C_0402]  118.83 101.8 90 top
CV99  0.1U_0402_16V4Z  [C_0402]  116.21 103.25 0 top
CV100  1U_0402_6.3V4Z  [C_0402]  111.09 110.52 270 top
CV101  1U_0402_6.3V4Z  [C_0402]  114.16 111.83 180 top
CV102  1U_0402_6.3V4Z  [C_0402]  109.83 113.94 90 top
CV103  1U_0402_6.3V4Z  [C_0402]  112.52 113.58 0 top
CV104  1U_0402_6.3V4Z  [C_0402]  109.65 107.93 270 top
CV105  1U_0402_6.3V4Z  [C_0402]  114.29 115.81 180 top
CV106  1U_0402_6.3V4Z  [C_0402]  110.15 116.59 270 top
CV107  1U_0402_6.3V4Z  [C_0402]  104.98 107.29 135 top
CV108  1U_0402_6.3V4Z  [C_0402]  105.29 104.83 315 top
CV109  1U_0402_6.3V4Z  [C_0402]  106 105.55 315 top
CV110  1U_0402_6.3V4Z  [C_0402]  103.69 106.07 135 top
CV111  1U_0402_6.3V4Z  [C_0402]  110.58 117.85 90 top
CV112  1U_0402_6.3V4Z  [C_0402]  115.88 109.1 90 top
CV113  1U_0402_6.3V4Z  [C_0402]  107.94 109.62 90 top
CV114  1U_0402_6.3V4Z  [C_0402]  111.09 108.37 270 top
CV115  1U_0402_6.3V4Z  [C_0402]  112.52 114.65 90 top
CV116  1U_0402_6.3V4Z  [C_0402]  111.63 116.45 0 top
CV117  1U_0402_6.3V4Z  [C_0402]  110.55 112.82 270 top
CV118  1U_0402_6.3V4Z  [C_0402]  112.85 109.8 270 top
CV119  1U_0402_6.3V4Z  [C_0402]  104.32 106.7 135 top
CV120  1U_0402_6.3V4Z  [C_0402]  111.27 119.96 90 top
CV121  1U_0402_6.3V4Z  [C_0402]  114.27 122.64 180 top
CV122  10U_0603_6.3V6M  [C_0603]  111.78 123.97 90 top
CV123  10U_0402_6.3V6M  [C_0402]  97.8 116.99 90 bottom
CV124  0.1U_0402_10V6K  [C_0402]  116.83 107.29 180 top
CV125  0.1U_0402_10V6K  [C_0402]  112.91 107.14 0 top
CV126  0.1U_0402_10V6K  [C_0402]  109.54 110.92 90 top
CV127  0.1U_0402_10V6K  [C_0402]  108.1 112.3 270 top
CV153  0.1U_0402_10V6K  [C_0402]  150.89 97.57 270 bottom
CV155  0.1U_0402_10V6K  [C_0402]  153.17 128.17 0 bottom
CV157  0.1U_0402_10V6K  [C_0402]  153.1 117.12 0 top
CV158  0.1U_0402_10V6K  [C_0402]  153.1 118.13 0 top
CV160  0.1U_0402_10V6K  [C_0402]  146.58 97.57 270 top
CV161  0.1U_0402_10V6K  [C_0402]  147.66 97.57 270 top
CV162  0.1U_0402_10V6K  [C_0402]  153.36 111.02 0 bottom
CV164  0.1U_0402_10V6K  [C_0402]  148.74 97.57 270 top
CV165  0.1U_0402_10V6K  [C_0402]  138.39 97.57 270 bottom
CV166  0.1U_0402_10V6K  [C_0402]  153.36 108.86 0 bottom
CV169  1U_0402_6.3V4Z  [C_0402]  153.36 107.78 0 bottom
CV170  1U_0402_6.3V4Z  [C_0402]  153.36 106.7 0 bottom
CV173  1U_0402_6.3V4Z  [C_0402]  153.36 105.62 0 bottom
CV174  0.01U_0402_16V7K  [C_0402]  125.56 127.32 90 top
CV175  0.01U_0402_16V7K  [C_0402]  116.24 112.77 180 top
CV176  0.01U_0402_16V7K  [C_0402]  117.73 108.01 90 top
CV177  0.01U_0402_16V7K  [C_0402]  119.26 107.92 90 top
CV178  0.01U_0402_16V7K  [C_0402]  117.55 111.24 90 top
CV179  0.01U_0402_16V7K  [C_0402]  99.32 112.54 0 top
CV180  1U_0402_6.3V4Z  [C_0402]  115.16 117.98 180 top
CV181  1U_0402_6.3V4Z  [C_0402]  112.16 117.46 90 top
CV198  0.1U_0402_10V6K  [C_0402]  153.1 121.25 0 top
CV210  0.1U_0402_10V6K  [C_0402]  152.3 130 90 top
CV211  0.1U_0402_10V6K  [C_0402]  150.4 130 90 top
CV213  0.1U_0402_10V6K  [C_0402]  147.5 129.98 90 top
CV216  0.1U_0402_10V6K  [C_0402]  148.74 97.57 270 bottom
CV219  0.1U_0402_10V6K  [C_0402]  147.66 97.57 270 bottom
CV221  0.1U_0402_10V6K  [C_0402]  153.36 99.72 0 top
CV225  10U_0603_6.3V6M  [C_0603]  153.18 97.5 270 top
CV227  1U_0402_6.3V4Z  [C_0402]  153.36 109.94 0 top
CV230  0.1U_0402_10V6K  [C_0402]  153.17 129.18 0 bottom
CV233  0.1U_0402_10V6K  [C_0402]  153.17 128.17 0 top
CV235  0.1U_0402_10V6K  [C_0402]  153.17 129.18 0 top
CV238  10U_0603_6.3V6M  [C_0603]  141.92 130.01 90 top
CV242  1U_0402_6.3V4Z  [C_0402]  148.46 129.98 90 top
CV243  1U_0402_6.3V4Z  [C_0402]  149.42 130 90 top
CV247  1U_0402_6.3V4Z  [C_0402]  146.55 129.98 90 top
CV248  1U_0402_6.3V4Z  [C_0402]  151.36 130 90 top
CV304  0.22U_0402_16V7K  [C_0402]  103.39 134.45 180 bottom
CV305  0.22U_0402_16V7K  [C_0402]  106.98 127.62 90 bottom
CV306  0.22U_0402_16V7K  [C_0402]  105.17 128.56 90 bottom
CV307  0.22U_0402_16V7K  [C_0402]  104.28 131.28 135 bottom
CV308  0.22U_0402_16V7K  [C_0402]  106.08 127.62 90 bottom
CV309  0.22U_0402_16V7K  [C_0402]  104.92 131.91 135 bottom
CV312  0.22U_0402_16V7K  [C_0402]  104.27 128.56 90 bottom
CV313  0.22U_0402_16V7K  [C_0402]  103.39 133.55 180 bottom
CV333  1U_0402_6.3V4Z  [C_0402]  139.46 97.57 270 bottom
CV334  1U_0402_6.3V4Z  [C_0402]  150.89 97.57 270 top
CV335  1U_0402_6.3V4Z  [C_0402]  153.36 99.72 0 bottom
CV336  1U_0402_6.3V4Z  [C_0402]  153.36 98.64 0 bottom
CV341  1U_0402_6.3V4Z  [C_0402]  153.17 130.2 0 bottom
CV342  1U_0402_6.3V4Z  [C_0402]  153.1 119.15 0 bottom
CV343  1U_0402_6.3V4Z  [C_0402]  153.1 120.17 0 bottom
CV344  1U_0402_6.3V4Z  [C_0402]  153.1 121.25 0 bottom
CV390  1U_0402_6.3V6K  [C_0402]  153.36 102.77 0 top
CV391  1U_0402_6.3V6K  [C_0402]  143.72 97.57 270 bottom
CV394  1U_0402_6.3V6K  [C_0402]  153.1 125.31 0 top
CV395  1U_0402_6.3V6K  [C_0402]  144.65 129.98 90 bottom
CW1  .1U_0402_16V7K  [C_0402]  44.66 96.43 90 bottom
CW2  .1U_0402_16V7K  [C_0402]  43.77 96.43 90 bottom
CW3  .1U_0402_16V7K  [C_0402]  60.7 104.01 270 top
CW4  .1U_0402_16V7K  [C_0402]  59.81 104.01 270 top
CW5  10U_0603_6.3V6M  [C_0603]  58.72 104.51 270 top
CW6  10U_0603_6.3V6M  [C_0603]  60.72 108.8 180 top
CW7  .1U_0402_16V7K  [C_0402]  60.8 109.88 180 top
CW8  .1U_0402_16V7K  [C_0402]  43.39 108.24 270 top
CW9  10P_0402_50V8J  [C_0402]  44.28 108.23 270 top
CX1  0.1U_0402_10V6K  [C_0402]  220.86 50.57 0 top
CX2  1U_0402_6.3V6K  [C_0402]  214.38 49.81 0 top
CX3  2200P_0402_25V7K  [C_0402]  215.3 51.65 180 top
CX4  0.01U_0402_16V7K  [C_0402]  207.52 42.51 0 bottom
CX5  0.1U_0402_10V6K  [C_0402]  215.61 37.55 180 bottom
CX6  0.1U_0402_10V6K  [C_0402]  207.52 40.73 0 bottom
CX7  0.1U_0402_10V6K  [C_0402]  207.52 41.62 0 bottom
CX8  0.1U_0402_10V6K  [C_0402]  207.52 38.95 0 bottom
CX9  0.1U_0402_10V6K  [C_0402]  216.54 40.28 0 bottom
CX10  0.1U_0402_10V6K  [C_0402]  207.52 39.84 0 bottom
CX11  0.1U_0402_10V6K  [C_0402]  216.54 39.39 0 bottom
CX12  12P_0402_50V8J  [C_0402]  220.86 51.46 0 top
CX13  12P_0402_50V8J  [C_0402]  215.3 50.7 180 top
CZ1  0.1U_0402_10V7K  [C_0402]  137.24 31.76 0 top
CZ2  0.1U_0402_10V7K  [C_0402]  131.84 35.05 270 top
CZ3  470P_0402_50V7K  [C_0402]  134.19 36.02 90 top
CZ4  1U_0402_6.3V6K  [C_0402]  135.79 27.16 270 top
CZ5  0.1U_0402_10V7K  [C_0402]  136.99 28.99 270 top
CZ6  0.1U_0402_10V7K  [C_0402]  133.99 25.55 0 top
CZ7  0.1U_0402_10V7K  [C_0402]  136.99 29.86 90 top
CZ8  0.1U_0402_25V6  [C_0402]  133.47 20.88 0 top
CZ9  0.1U_0402_10V7K  [C_0402]  169.25 21.7 90 top
CZ10  470P_0402_50V7K  [C_0402]  166.39 20.15 270 top
CZ11  470P_0402_50V7K  [C_0402]  165.5 20.15 270 top
CZ12  0.1U_0402_10V7K  [C_0402]  164.57 17.33 0 top
CZ13  0.1U_0402_16V7K  [C_0402]  129.28 92.67 180 bottom
CZ14  100P_0402_50V8J  [C_0402]  125.33 91.46 180 bottom
CZ15  0.1U_0402_16V7K  [C_0402]  118.84 93.37 180 bottom
CZ16  0.1U_0402_16V7K  [C_0402]  118.84 89.79 180 bottom
CZ17  1U_0402_6.3V6K  [C_0402]  115.86 89.81 180 bottom
CZ18  330P_0402_50V7K  [C_0402]  111.78 92.44 0 bottom
CZ19  330P_0402_50V7K  [C_0402]  111.79 91.57 0 bottom
CZ20  0.1U_0402_10V7K  [C_0402]  110.47 87.5 90 bottom
CZ21  1U_0402_6.3V6K  [C_0402]  131.81 32.36 90 top
CZ22  0.1U_0402_10V7K  [C_0402]  135.52 34.52 0 top
CZ23  1U_0402_6.3V6K  [C_0402]  168.19 25.49 90 top
CZ25  1U_0402_6.3V6K  [C_0402]  166.01 26.37 0 top
CZ26  1U_0402_6.3V6K  [C_0402]  129.27 94.38 90 bottom
CZ27  0.1U_0402_10V7K  [C_0402]  127.55 91.23 180 bottom
CZ28  0.1U_0402_10V7K  [C_0402]  124.87 94.91 0 bottom
CZ29  1U_0402_6.3V6K  [C_0402]  115.58 94.46 180 bottom
CZ30  0.1U_0402_10V7K  [C_0402]  117.93 91.59 0 bottom
CZ31  0.1U_0402_10V7K  [C_0402]  113.41 95.28 90 bottom
D1  -  [BAS40C_SOT23-3]  35.36 3.33 90 bottom
D2  -  [RB551V-30_SOD323-2]  36.4 7.52 270 top
D3  -  [BAT54C-7-F_SOT23-3]  222.55 22.38 90 top
D4  -  [BAT54C-7-F_SOT23-3]  222.55 22.38 270 bottom
D5  -  [RB551V-30_SOD323-2]  217.82 30.5 0 top
D6  -  [RB551V-30_SOD323-2]  99.59 5.67 90 top
D8  -  [SDMK0340L-7-F_SOD323-2]  184.19 53.59 135 top
DA1  AZ5125-02S.R7G_SOT23-3  [AZ5125-02SPR7G_SOT23-3]  24.82 7.2 270 top
DA2  AZ5125-02S.R7G_SOT23-3  [AZ5125-02SPR7G_SOT23-3]  25.2 3.2 270 top
DA3  -  [BAT54C-7-F_SOT23-3]  17.58 31.13 270 top
DA4  -  [L03ESDL5V0CC3-2_SOT23-3]  18.84 12.09 270 bottom
DA5  AZ5123-02S.R7G_SOT23-3  [AZ5123-02SPR7G_SOT23-3]  18.84 16.15 270 bottom
DA6  -  [PESD5V0U2BT_SOT23-3]  220.36 29.02 180 bottom
DE1  AZ5125-01H.R7G_SOD523-2  [AZ5125-01HPR7G_SOD523-2]  158.5 16.15 180 top
DX1  S DIO(BR) TVWDF1004AD0 DFN ESD  [IP4292CZ10-TBR_XSON10_2P5X1]  218.67 45.64 180 bottom
DX2  -  [RB751S40T1G_SOD523-2]  104.1 30.19 270 top
DX3  -  [RB751S40T1G_SOD523-2]  105.24 29.24 270 top
DZ1  -  [RB751S40T1G_SOD523-2]  91.01 33.17 0 top
DZ2  -  [RB751S40T1G_SOD523-2]  138 27.64 90 top
DZ3  -  [RB751S40T1G_SOD523-2]  92.32 17.3 90 top
DZ4  -  [RB751S40T1G_SOD523-2]  89.87 10.48 90 top
DZ5  -  [RB751S40T1G_SOD523-2]  135.39 33.03 270 top
EC2201  0.1U_0402_25V6  [C_0402]  165.07 109.18 180 bottom
EC2202  1000P_0402_50V7K  [C_0402]  197.25 27.63 90 bottom
EC2203  0.1U_0402_25V6  [C_0402]  156.52 102.34 180 bottom
EC2204  1000P_0402_50V7K  [C_0402]  62.57 132.75 270 top
EC2205  0.1U_0402_25V6  [C_0402]  168.36 133.81 90 bottom
EC2206  0.1U_0402_25V6  [C_0402]  104.98 135.42 270 bottom
EC2207  1000P_0402_50V7K  [C_0402]  102.83 135.22 270 top
EC2208  1000P_0402_50V7K  [C_0402]  165.07 108.16 180 bottom
EC2209  1000P_0402_50V7K  [C_0402]  121.49 130.02 270 bottom
EC2210  0.1U_0402_25V6  [C_0402]  149.25 133.8 90 top
EC2211  0.1U_0402_25V6  [C_0402]  172.5 59.9 180 bottom
EC2212  1000P_0402_50V7K  [C_0402]  226.88 43.6 270 top
EC2213  1000P_0402_50V7K  [C_0402]  123.72 129.82 270 top
EC2214  1000P_0402_50V7K  [C_0402]  159.34 46.94 90 bottom
EC2215  1U_0402_10V6K  [C_0402]  166.4 18.38 180 top
EC2216  1U_0402_10V6K  [C_0402]  204.86 16.03 270 top
EC2222  0.1U_0402_25V6  [C_0402]  83.32 113.68 0 top
EC2223  0.1U_0402_25V6  [C_0402]  103.77 103.03 315 top
EC2225  1U_0402_10V6K  [C_0402]  128.35 94.37 90 bottom
EC2226  1U_0402_10V6K  [C_0402]  49.22 17.04 90 top
EC2229  1U_0402_10V6K  [C_0402]  176.12 23.15 270 top
EC2230  1U_0402_10V6K  [C_0402]  156.03 110.3 180 top
EC2301  0.1U_0402_25V6  [C_0402]  13.1 10.13 270 top
EC2302  0.1U_0402_25V6  [C_0402]  16.27 24.2 90 top
EC2901  1000P_0402_50V7K  [C_0402]  156.5 104.54 180 top
EC2902  .1U_0402_16V7K  [C_0402]  155.98 108.12 180 top
EC3001  .1U_0402_16V7K  [C_0402]  115.45 4.47 0 top
EC3002  .1U_0402_16V7K  [C_0402]  120.53 9.42 0 bottom
EC3201  33P_0402_50V8J  [C_0402]  55.26 98.25 0 bottom
EC3202  33P_0402_50V8J  [C_0402]  54.4 98.25 180 bottom
ED2901  -  [AZ5725-01F_DFN2]  157.29 101.19 180 top
EU2601  -  [L05ESDL5V0NA-4_SLP2510P8-10-9]  18.17 60.17 270 top
EU2602  -  [AZC199-02SPR7G_SOT23-3]  17.77 57.36 270 top
EU2603  -  [L05ESDL5V0NA-4_SLP2510P8-10-9]  18.17 38.52 270 top
EU2604  -  [AZC199-02SPR7G_SOT23-3]  18.09 35.65 270 top
EU3101  -  [L05ESDL5V0NA-4_SLP2510P8-10-9]  196.7 19.63 180 bottom
EU3501  -  [TVWDF1004AD0_DFN9]  30.57 109.32 90 bottom
F1  SMD1812P150TF/24 1.5A UL/CSA/TUV  [F_SMD1812P110TF-24]  227.39 45.56 90 top
F2  1.1A_24V_SMD1812P110TF-24  [F_SMD1812P110TF-24]  229.52 32.41 180 top
F3  0.5A_13.2V_MF-NSMF050-2  [F_MF-NSMF050-2]  120.99 7.05 270 bottom
FD1  FIDUCAL  [FIDUCIAL_C40M80]  44.79 133.38 0 top
FD2  FIDUCAL  [FIDUCIAL_C40M80]  14.54 99.18 180 bottom
FD3  FIDUCAL  [FIDUCIAL_C40M80]  211.26 10.99 0 top
FD4  FIDUCAL  [FIDUCIAL_C40M80]  174.23 2.72 180 bottom
FI1  1.5A_6V_1206L150PR~D  [F_1206L150PR]  21.86 95.97 0 top
H1  HOLEA  [H_3P0-G]  18.4 4.3 0 bottom
H2  HOLEA  [H_3P0-G]  8.7 122.3 180 bottom
H3  HOLEA  [H_3P0-G]  141.9 6.3 180 bottom
H4  HOLEA  [H_3P0-G]  206.6 47.9 180 bottom
H5  HOLEA  [H_3P0-G]  141.9 61.2 180 bottom
H6  HOLEA  [H_5P6N]  18.3 94.3 180 bottom
H7  HOLEA  [H_3P0N]  3 122.3 180 bottom
H8  HOLEA  [H_3P5]  88.93 117.7 180 bottom
H9  HOLEA  [H_3P5]  113.5 134.5 180 bottom
H10  HOLEA  [H_3P5]  136.5 90.5 180 bottom
H11  HOLEA  [H_3P2]  52.3 133.7 180 bottom
H12  HOLEA  [H_3P2X2P6]  5 3.6 270 bottom
H13  HOLEA  [H_6P0]  121.2 136 180 bottom
HCPU1  HOLEA  [H_3P7X4P3]  100 80.45 180 bottom
HCPU2  HOLEA  [H_3P9]  124.3 80.45 180 bottom
HCPU3  HOLEA  [H_3P7]  100 17.25 180 bottom
HCPU4  HOLEA  [H_3P7X4P3]  124.3 17.25 270 bottom
J3D1  ACES_50463-0104A-001  [ACES_50463-0104A-001_10P]  219 49.12 0 bottom
JCMOS1  SHORT PADS~D  [SHORTPADS]  88.03 17.04 0 bottom
JDB1  JXT_FP241AH-010GAAM  [JXT_FP241AH-010GAAM_10P]  118.74 7.95 0 top
JDEG1  JXT_FP241AH-010GAAM  [JXT_FP241AH-010GAAM_10P]  129.72 7.96 0 top
JDIMM1  DEREN_40-42271-26001RHF  [DEREN_40-42271-26001RHF_260P-T]  67.25 87.13 270 bottom
JDIMM2  DEREN_40-42261-26001RHF  [DEREN_40-42261-26001RHF_260P-T]  53.05 87.62 90 bottom
JEDP1  ACES_51540-04001-P01  [ACES_51540-04001-P01_40P]  224.07 50.05 270 bottom
JFAN1  JXT_WB247H-004S10M  [JXT_WB247H-004S10M_4P]  182.78 52.11 47.5 bottom
JHDD1  ACES_51625-01201-001  [ACES_51625-01201-001_12P]  199.15 17.07 180 bottom
JHDMI1  CONCR_099AKAC19NBLCNF  [CONCR_099AKAC19NBLCNF_19P]  10.45 82.5 90 bottom
JHP1  YUQIU_PJ753-F07J1BE-B  [YUQIU_PJ753-F07J1BE-B_7P-T]  11.55 13.52 90 bottom
JIOB1  ACES_51524-0160N-001  [ACES_51524-0160N-001_16P]  185.6 17.58 180 bottom
JKB1  STARC_132C30-100020-A2-R  [STARC_132C30-100020-A2-R_30P]  87.81 9.29 180 bottom
JKBBL1  ACES_51575-00401-001  [ACES_51575-00401-001_4P-T]  116.11 8.95 180 bottom
JLAN1  SANTA_130460-N  [SANTA_130460-N_8P-T]  12.85 113.27 90 bottom
JLED1  ACES_51524-0040N-001  [ACES_51524-0040N-001_4P]  153.7 12.44 180 bottom
JODD1  ACES_50673-0120N-001  [ACES_50673-0120N-001_12P-T]  187.5 47.74 180 bottom
JP1  -  [JUMP_43X79]  133.18 23.94 270 top
JP2  PAD-OPEN1X1M  [JUMP_43X39]  132.48 37.18 270 top
JP4  PAD-OPEN1X3M  [JUMP_43X118]  169.45 17.37 90 top
JP5  PAD-OPEN1X3M  [JUMP_43X118]  162.8 18.1 180 top
JP6  -  [JUMP_43X118]  122.63 93.46 180 bottom
JP7  -  [JUMP_43X118]  108.95 95.04 90 bottom
JP8  PAD-OPEN1X2M  [JUMP_43X39]  110.45 90 180 bottom
JP9  -  [JUMP_43X79]  162.52 27.41 180 top
JP10  -  [JUMP_43X39]  220.38 48.96 180 top
JP11  2MM  [JUMP_43X39]  30.6 121.39 90 bottom
JP12  -  [JUMP_43X79]  202.01 17.83 90 top
JP13  -  [JUMP_43X79]  194.58 47.14 90 top
